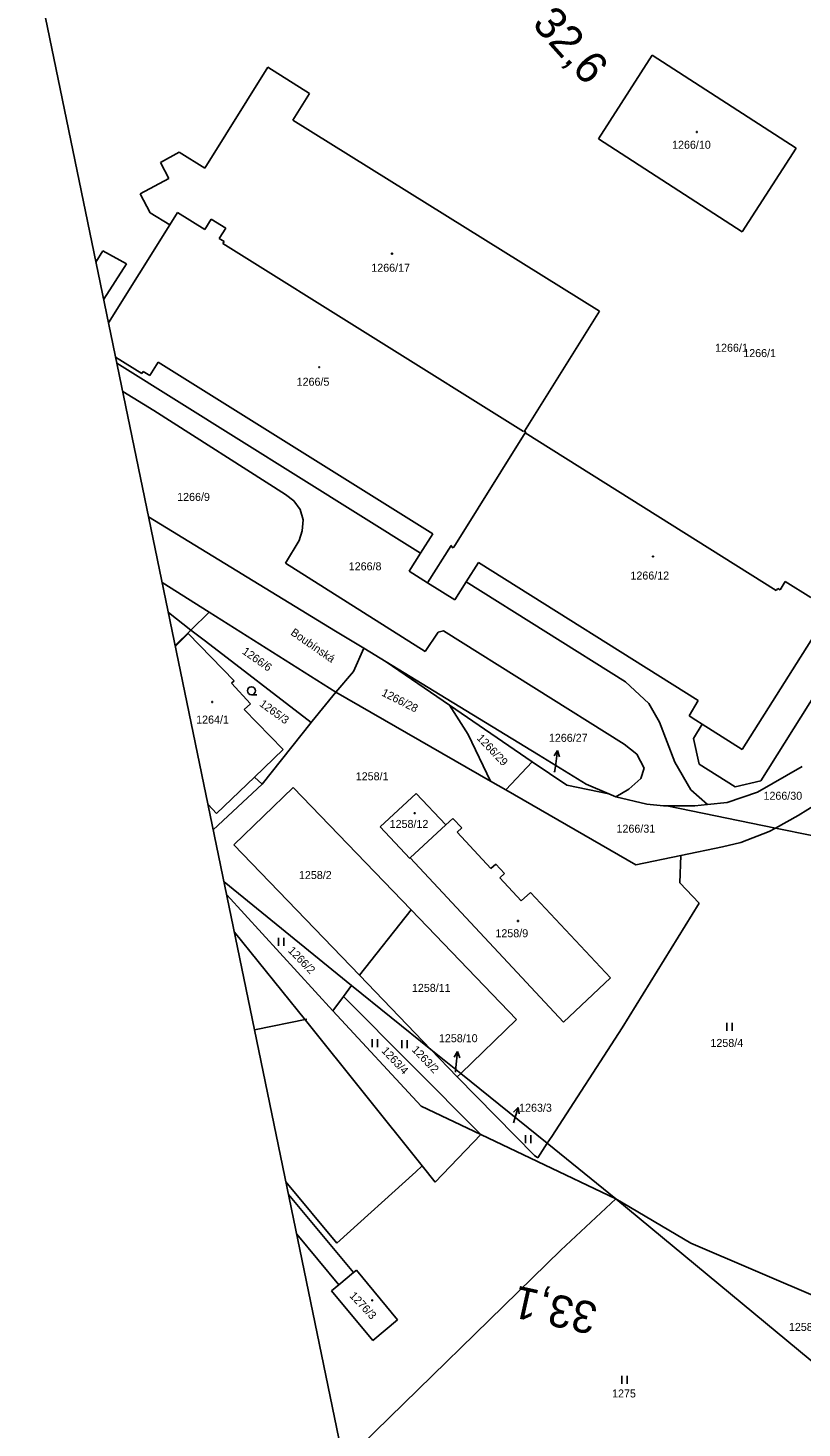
# Model space of a CAD drawing. Extents: x -804166 to -803706, y -1151030 to -1150147.
# Drawn here: x -804123.8 to -803978.8, y -1150693.3 to -1150430.9 of the extents above; entities that cross this region are included whole.
import ezdxf

# ---------------------------------------------------------------- set-up
doc = ezdxf.new("R2010")
doc.units = 0
for name, color, linetype in [('Default', 7, 'Continuous'), ('formát', 7, 'Continuous'), ('kilometráž - vrstava 7', 7, 'Continuous'), ('kn_celek - Cisla parcel pomocna', 7, 'Continuous'), ('kn_celek - Cisla pozemkovych parcel', 7, 'Continuous'), ('kn_celek - Cisla stavebnich parcel', 7, 'Continuous'), ('kn_celek - Dalsi prvky mapy popis', 7, 'Continuous'), ('kn_celek - Hranice parcel', 7, 'Continuous'), ('kn_celek - Vnitrni kresby', 7, 'Continuous'), ('kn_celek - Znacky budov', 7, 'Continuous'), ('kn_celek - Znacky kultur', 7, 'Continuous')]:
    doc.layers.add(name, color=color, linetype=linetype)

# ---------------------------------------------------------------- blocks, each defined once
blk = doc.blocks.new('306')
at = {"layer": 'Default'}
for p, q in [((-5.2, 0), (-5.2, 15)), ((4.8, 0), (4.8, 15))]:
    blk.add_line(p, q, dxfattribs=at)
blk = doc.blocks.new('304')
at = {"layer": 'Default'}
blk.add_line((-0.1, 0), (9.9, 0), dxfattribs=at)
blk.add_circle((-0.1, 7.5), 7.5, dxfattribs=at)
blk = doc.blocks.new('402')
at = {"layer": 'Default'}
for p, q in [((-0.8, 0.8), (0.7, 0.8)), ((-0.8, 0.8), (-0.8, -0.7)), ((0.7, 0.8), (0.7, -0.7)), ((0.7, -0.7), (-0.8, -0.7))]:
    blk.add_line(p, q, dxfattribs=at)
blk = doc.blocks.new('Z61')
at = {"layer": 'Default'}
for p, q in [((0, 0), (30, 0)), ((30, 0), (19.2, 5.3)), ((30, 0), (19.2, -5.3))]:
    blk.add_line(p, q, dxfattribs=at)

msp = doc.modelspace()

# ---------------------------------------------------------------- linework, layer by layer
at = {"layer": 'formát'}
for p, q in [((-804123.84, -1150413.06), (-804081.38, -1150618.72)), ((-804081.38, -1150618.72), (-804071.58, -1150616.7)), ((-804081.38, -1150618.72), (-803996.46, -1151030.05))]:
    msp.add_line(p, q, dxfattribs=at)
at = {"layer": 'kn_celek - Cisla parcel pomocna'}
for p, q in [((-804025.16, -1150570.39), (-804025.01, -1150569.34)), ((-804043.76, -1150626.64), (-804043.67, -1150625.78))]:
    msp.add_line(p, q, dxfattribs=at)
at = {"layer": 'kn_celek - Hranice parcel'}
for p, q in [((-804016.96, -1150451.69), (-804006.87, -1150436.01)), ((-804006.87, -1150436.01), (-803979.87, -1150453.43)), ((-804078.92, -1150438.26), (-804090.73, -1150457.18)), ((-804071.08, -1150443.16), (-804078.92, -1150438.26)), ((-804074.21, -1150448.18), (-804071.08, -1150443.16)), ((-804016.75, -1150484.01), (-804074.21, -1150448.18)), ((-803989.99, -1150469.12), (-804016.96, -1150451.69)), ((-804095.54, -1150454.21), (-804099.03, -1150456.1)), ((-804090.73, -1150457.18), (-804095.54, -1150454.21)), ((-803979.87, -1150453.43), (-803989.99, -1150469.12)), ((-804099.03, -1150456.1), (-804097.43, -1150459.12)), ((-804097.43, -1150459.12), (-804102.83, -1150461.99)), ((-804102.83, -1150461.99), (-804100.93, -1150465.54)), ((-804100.93, -1150465.54), (-804097.27, -1150467.82)), ((-804095.82, -1150465.49), (-804097.27, -1150467.82)), ((-804090.73, -1150468.69), (-804095.82, -1150465.49)), ((-804097.27, -1150467.82), (-804108.74, -1150486.17)), ((-804089.52, -1150466.74), (-804090.73, -1150468.69)), ((-804086.8, -1150468.43), (-804089.52, -1150466.74)), ((-804088.02, -1150470.38), (-804086.8, -1150468.43)), ((-804087.09, -1150470.96), (-804088.02, -1150470.38)), ((-804087.3, -1150471.3), (-804087.09, -1150470.96)), ((-804030.97, -1150506.52), (-804087.3, -1150471.3)), ((-804109.79, -1150472.7), (-804111.1, -1150474.78)), ((-804105.4, -1150475.1), (-804109.79, -1150472.7)), ((-804105.4, -1150475.1), (-804109.66, -1150481.72)), ((-804030.79, -1150506.51), (-804016.75, -1150484.01)), ((-804107.42, -1150492.59), (-804102.5, -1150495.66)), ((-804107.19, -1150493.72), (-804050.27, -1150529.35)), ((-804101.02, -1150496.07), (-804099.45, -1150493.57)), ((-804099.45, -1150493.57), (-804047.98, -1150525.74)), ((-804102.5, -1150495.66), (-804102.29, -1150495.28)), ((-804102.29, -1150495.28), (-804101.02, -1150496.07)), ((-804106.09, -1150499.03), (-804100.25, -1150502.6)), ((-804100.25, -1150502.6), (-804075.6, -1150518.36)), ((-804030.68, -1150506.78), (-804044.05, -1150528.23)), ((-804030.92, -1150506.44), (-804030.97, -1150506.52)), ((-804030.92, -1150506.44), (-804030.79, -1150506.51)), ((-804030.79, -1150506.51), (-804030.58, -1150506.63)), ((-804030.68, -1150506.78), (-804030.58, -1150506.63)), ((-803983.63, -1150536.38), (-804030.68, -1150506.78)), ((-804075.6, -1150518.36), (-804074.02, -1150519.53)), ((-804074.02, -1150519.53), (-804072.81, -1150521.15)), ((-804072.81, -1150521.15), (-804072.3, -1150523.12)), ((-804066.19, -1150543.95), (-804101.24, -1150522.52)), ((-804072.3, -1150523.12), (-804072.44, -1150525.14)), ((-804072.44, -1150525.14), (-804073.01, -1150527.01)), ((-804047.98, -1150525.74), (-804050.27, -1150529.35)), ((-804073.01, -1150527.01), (-804075.59, -1150531.2)), ((-804044.52, -1150527.91), (-804048.97, -1150534.9)), ((-804044.52, -1150527.91), (-804044.39, -1150527.99)), ((-804044.39, -1150527.99), (-804044.48, -1150528.14)), ((-804044.48, -1150528.14), (-804044.14, -1150528.37)), ((-804044.14, -1150528.37), (-804044.05, -1150528.23)), ((-804075.59, -1150531.2), (-804049.42, -1150547.8)), ((-804052.42, -1150532.75), (-804050.27, -1150529.35)), ((-804039.43, -1150531.11), (-804041.71, -1150534.74)), ((-803998.28, -1150556.97), (-804039.43, -1150531.11)), ((-804052.42, -1150532.75), (-804048.97, -1150534.9)), ((-804089.88, -1150540.41), (-804098.7, -1150534.84)), ((-804043.84, -1150538.13), (-804048.97, -1150534.9)), ((-804041.71, -1150534.74), (-804043.84, -1150538.13)), ((-804041.71, -1150534.74), (-804011.88, -1150553.48)), ((-803983.36, -1150535.95), (-803983.63, -1150536.38)), ((-803982.92, -1150536.23), (-803983.36, -1150535.95)), ((-803981.93, -1150534.66), (-803982.92, -1150536.23)), ((-803977.17, -1150537.66), (-803981.93, -1150534.66)), ((-804097.53, -1150540.5), (-804093.31, -1150543.76)), ((-804089.88, -1150540.41), (-804093.31, -1150543.76)), ((-804089.88, -1150540.41), (-804066.17, -1150555.39)), ((-804096.26, -1150546.65), (-804093.31, -1150543.76)), ((-804096.23, -1150546.77), (-804093.82, -1150544.42)), ((-804093.82, -1150544.42), (-804085.19, -1150553.27)), ((-804093.31, -1150543.76), (-804090.57, -1150545.83)), ((-804060.93, -1150547.17), (-804066.19, -1150543.95)), ((-804049.42, -1150547.8), (-804046.98, -1150544.17)), ((-804046.98, -1150544.17), (-804045.99, -1150543.91)), ((-804045.99, -1150543.91), (-804012.15, -1150565.18)), ((-804090.57, -1150545.83), (-804070.79, -1150561.09)), ((-804062.82, -1150551.55), (-804060.93, -1150547.17)), ((-804056.75, -1150549.72), (-804060.93, -1150547.17)), ((-803986.49, -1150572.01), (-803969.82, -1150545.4)), ((-804045.51, -1150556.6), (-804056.75, -1150549.72)), ((-804044.84, -1150557.87), (-804056.75, -1150549.72)), ((-804066.17, -1150555.39), (-804062.82, -1150551.55)), ((-804085.19, -1150553.27), (-804085.71, -1150553.75)), ((-804085.71, -1150553.75), (-804082.14, -1150557.58)), ((-804070.57, -1150560.82), (-804066.17, -1150555.39)), ((-804037.19, -1150572.09), (-804066.17, -1150555.39)), ((-804011.88, -1150553.48), (-804007.48, -1150557.53)), ((-804082.14, -1150557.58), (-804083.36, -1150558.66)), ((-804028.2, -1150567.18), (-804045.51, -1150556.6)), ((-804044.84, -1150557.87), (-804041.37, -1150563.36)), ((-804029.38, -1150568.44), (-804044.84, -1150557.87)), ((-804007.48, -1150557.53), (-804005.51, -1150561.04)), ((-803999.95, -1150559.82), (-803998.28, -1150556.97)), ((-804083.36, -1150558.66), (-804076.02, -1150566.18)), ((-803998.67, -1150560.68), (-803999.95, -1150559.82)), ((-803998.67, -1150560.68), (-803997.49, -1150561.43)), ((-804070.79, -1150561.09), (-804079.95, -1150572.68)), ((-804070.57, -1150560.82), (-804070.79, -1150561.09)), ((-804005.51, -1150561.04), (-804002.65, -1150568.53)), ((-803997.49, -1150561.43), (-803999.16, -1150564.07)), ((-804041.37, -1150563.36), (-804037.19, -1150572.09)), ((-804012.15, -1150565.18), (-804009.78, -1150567.05)), ((-803999.16, -1150564.07), (-803998.05, -1150568.92)), ((-804081.39, -1150571.32), (-804076.02, -1150566.18)), ((-804029.38, -1150568.44), (-804034.33, -1150573.74)), ((-804022.9, -1150572.87), (-804029.38, -1150568.44)), ((-804019.25, -1150572.65), (-804028.2, -1150567.18)), ((-804009.78, -1150567.05), (-804008.4, -1150569.67)), ((-804002.65, -1150568.53), (-803999.61, -1150573.7)), ((-804008.4, -1150569.67), (-804009.02, -1150571.59)), ((-803998.05, -1150568.92), (-803991.34, -1150573.13)), ((-803987.15, -1150574.13), (-803978.76, -1150569.37)), ((-804079.95, -1150572.68), (-804089.12, -1150581.24)), ((-804081.39, -1150571.32), (-804088.5, -1150578.14)), ((-804085.27, -1150584), (-804074.15, -1150573.25)), ((-804079.95, -1150572.68), (-804081.39, -1150571.32)), ((-804074.15, -1150573.25), (-804052.05, -1150596.22)), ((-804034.33, -1150573.74), (-804037.19, -1150572.09)), ((-804009.91, -1150587.8), (-804034.33, -1150573.74)), ((-804015.03, -1150574.48), (-804022.9, -1150572.87)), ((-804019.25, -1150572.65), (-804015.03, -1150574.48)), ((-804011.25, -1150573.61), (-804013.7, -1150575.06)), ((-804009.02, -1150571.59), (-804011.25, -1150573.61)), ((-803999.61, -1150573.7), (-803996.54, -1150576.47)), ((-803991.34, -1150573.13), (-803986.49, -1150572.01)), ((-804057.86, -1150580.66), (-804051.13, -1150574.38)), ((-804051.13, -1150574.38), (-804045.54, -1150580.31)), ((-804015.03, -1150574.48), (-804013.7, -1150575.06)), ((-804013.7, -1150575.06), (-804007.87, -1150576.4)), ((-804007.87, -1150576.4), (-804004.78, -1150576.71)), ((-803996.54, -1150576.47), (-803992.85, -1150576.07)), ((-803987.15, -1150574.13), (-803992.85, -1150576.07)), ((-803974.11, -1150575.13), (-803979.5, -1150578.55)), ((-804088.5, -1150578.14), (-804090.1, -1150576.46)), ((-804004.78, -1150576.71), (-804004.14, -1150576.71)), ((-804004.14, -1150576.71), (-803998.89, -1150576.73)), ((-803983.74, -1150580.89), (-804004.14, -1150576.71)), ((-803998.89, -1150576.73), (-803996.54, -1150576.47)), ((-803979.5, -1150578.55), (-803983.74, -1150580.89)), ((-804052.31, -1150586.58), (-804057.86, -1150580.66)), ((-804052.2, -1150586.48), (-804045.54, -1150580.31)), ((-804045.54, -1150580.31), (-804044.21, -1150579.08)), ((-804044.21, -1150579.08), (-804042.55, -1150580.86)), ((-804042.55, -1150580.86), (-804043.44, -1150581.68)), ((-803990.24, -1150583.6), (-803984.93, -1150581.55)), ((-803984.93, -1150581.55), (-803983.74, -1150580.89)), ((-803983.74, -1150580.89), (-803976.96, -1150582.28)), ((-804061.72, -1150608.48), (-804085.27, -1150584)), ((-804043.44, -1150581.68), (-804037.1, -1150588.46)), ((-803993.73, -1150584.41), (-803990.24, -1150583.6)), ((-804052.2, -1150586.48), (-804052.31, -1150586.58)), ((-804023.47, -1150617.24), (-804052.2, -1150586.48)), ((-804009.91, -1150587.8), (-804001.51, -1150586.04)), ((-804001.71, -1150591.16), (-804001.51, -1150586.04)), ((-804001.51, -1150586.04), (-803993.73, -1150584.41)), ((-804037.1, -1150588.46), (-804036.2, -1150587.63)), ((-804036.2, -1150587.63), (-804034.55, -1150589.42)), ((-804034.55, -1150589.42), (-804035.44, -1150590.24)), ((-804063.22, -1150610.38), (-804087.1, -1150590.99)), ((-804035.44, -1150590.24), (-804031.43, -1150594.53)), ((-803998.09, -1150594.95), (-804001.71, -1150591.16)), ((-804086.61, -1150593.39), (-804066.74, -1150615.12)), ((-804031.43, -1150594.53), (-804029.68, -1150592.95)), ((-804029.68, -1150592.95), (-804014.66, -1150608.98)), ((-804052.05, -1150596.22), (-804061.72, -1150608.48)), ((-804052.05, -1150596.22), (-804032.3, -1150616.75)), ((-804012.48, -1150618.32), (-803998.09, -1150594.95)), ((-804071.82, -1150616.91), (-804085.16, -1150600.4)), ((-804064.75, -1150612.44), (-804063.22, -1150610.38)), ((-804063.22, -1150610.38), (-804048.33, -1150622.39)), ((-804048.33, -1150622.39), (-804061.72, -1150608.48)), ((-804014.66, -1150608.98), (-804023.47, -1150617.24)), ((-804066.74, -1150615.12), (-804064.75, -1150612.44)), ((-804064.75, -1150612.44), (-804038.96, -1150638.33)), ((-804050.17, -1150633), (-804066.74, -1150615.12)), ((-804071.82, -1150616.91), (-804049.99, -1150644.23)), ((-804032.3, -1150616.75), (-804042.74, -1150626.9)), ((-804025.71, -1150638.73), (-804012.48, -1150618.32)), ((-804043.39, -1150627.53), (-804048.33, -1150622.39)), ((-804042.74, -1150626.9), (-804048.33, -1150622.39)), ((-804042.74, -1150626.9), (-804043.39, -1150627.53)), ((-804028.9, -1150642.28), (-804043.39, -1150627.53)), ((-804042.74, -1150626.9), (-804026.54, -1150639.97)), ((-804038.96, -1150638.33), (-804050.17, -1150633)), ((-804047.57, -1150647.28), (-804038.96, -1150638.33)), ((-804028.35, -1150643.39), (-804038.96, -1150638.33)), ((-804026.54, -1150639.97), (-804025.71, -1150638.73)), ((-804028.32, -1150642.67), (-804026.54, -1150639.97)), ((-804026.54, -1150639.97), (-804013.68, -1150650.38)), ((-804051.16, -1150645.3), (-804049.99, -1150644.23)), ((-804049.99, -1150644.23), (-804047.57, -1150647.28)), ((-804028.32, -1150642.67), (-804028.9, -1150642.28)), ((-804013.68, -1150650.38), (-804028.35, -1150643.39)), ((-804075.5, -1150647.21), (-804065.98, -1150658.69)), ((-804065.98, -1150658.69), (-804051.16, -1150645.3)), ((-804075.01, -1150649.56), (-804062.82, -1150664.2)), ((-804013.68, -1150650.38), (-804024.02, -1150660)), ((-804013.68, -1150650.38), (-803999.62, -1150658.69)), ((-803968.03, -1150688.27), (-804013.68, -1150650.38)), ((-804073.47, -1150657.01), (-804065.57, -1150666.5)), ((-804024.02, -1150660), (-804064.66, -1150699.72)), ((-803999.62, -1150658.69), (-803974.99, -1150669.28)), ((-804065.57, -1150666.5), (-804062.82, -1150664.2)), ((-804062.82, -1150664.2), (-804062.31, -1150663.77)), ((-804062.31, -1150663.77), (-804054.58, -1150673.04)), ((-804066.95, -1150667.66), (-804065.57, -1150666.5)), ((-804059.21, -1150676.92), (-804066.95, -1150667.66)), ((-804054.58, -1150673.04), (-804059.21, -1150676.92))]:
    msp.add_line(p, q, dxfattribs=at)
at = {"layer": 'kn_celek - Vnitrni kresby'}
for p, q in [((-803989.99, -1150566.17), (-803974.91, -1150542.21)), ((-803997.49, -1150561.43), (-803989.99, -1150566.17))]:
    msp.add_line(p, q, dxfattribs=at)

# ---------------------------------------------------------------- block references
at = {"layer": 'kn_celek - Cisla parcel pomocna'}
for p, xscale, yscale, rotation in [((-804025.01, -1150569.34), 0.1, 0.09999999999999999, 81.9297), ((-804043.67, -1150625.78), 0.1, 0.10000000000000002, 84.05316000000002), ((-804032.88, -1150636.15), 0.09999999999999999, 0.09999999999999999, 73.30086000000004)]:
    msp.add_blockref('Z61', p, dxfattribs=dict(at, xscale=xscale, yscale=yscale, rotation=rotation))
at = {"layer": 'kn_celek - Znacky budov', "xscale": 0.1, "yscale": 0.10000000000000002}
for p in [(-803998.51, -1150450.4), (-804055.62, -1150473.21), (-804069.28, -1150494.51), (-804006.72, -1150529.99), (-804089.33, -1150557.27), (-804051.39, -1150578.08), (-804032.02, -1150598.31), (-804059.35, -1150669.41)]:
    msp.add_blockref('402', p, dxfattribs=at)
at = {"layer": 'kn_celek - Znacky kultur', "xscale": 0.1, "yscale": 0.10000000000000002}
for name, p in [('304', (-804081.95, -1150555.89)), ('306', (-804076.37, -1150602.99)), ('306', (-803992.4, -1150618.9)), ('306', (-804058.82, -1150621.97)), ('306', (-804053.28, -1150622.16)), ('306', (-804030.09, -1150639.93)), ('306', (-804012.07, -1150685.07))]:
    msp.add_blockref(name, p, dxfattribs=at)

# ---------------------------------------------------------------- texts
at = {"layer": 'kilometráž - vrstava 7'}
for s, rotation, p in [('32,6', 311.8828, (-804029.55, -1150430.27)), ('33,1', 167.4012, (-804016.8, -1150670.05))]:
    msp.add_text(s, height=6, rotation=rotation, dxfattribs=at).set_placement(p)
at = {"layer": 'kn_celek - Cisla parcel pomocna'}
for s, p in [('1266/27', (-804026.23, -1150564.72)), ('1258/10', (-804046.84, -1150621.03)), ('1263/3', (-804031.81, -1150634.06))]:
    msp.add_text(s, height=1.5, dxfattribs=at).set_placement(p)
at = {"layer": 'kn_celek - Cisla pozemkovych parcel'}
for s, height, p in [('1266/1', 1.5, (-803995.09, -1150491.6)), ('1266/1', 1.5, (-803989.81, -1150492.6)), ('1266/9', 1.5, (-804095.89, -1150519.56)), ('1266/8', 1.5, (-804063.74, -1150532.57)), ('1258/1', 1.5, (-804062.42, -1150571.93)), ('1266/27', 0.1, (-804025.47, -1150570.36)), ('1266/30', 1.5, (-803986.02, -1150575.58)), ('1266/31', 1.5, (-804013.56, -1150581.74)), ('1258/2', 1.5, (-804073.07, -1150590.44)), ('1258/11', 1.5, (-804051.9, -1150611.59)), ('1258/4', 1.5, (-803995.96, -1150621.91)), ('1258/10', 0.1, (-804044.06, -1150626.61)), ('1263/3', 0.1, (-804032.88, -1150636.12)), ('1258/5', 1.5, (-803981.26, -1150675.15)), ('1275', 1.5, (-804014.39, -1150687.62))]:
    msp.add_text(s, height=height, dxfattribs=at).set_placement(p)
for s, rotation, p in [('1266/6', 324.9, (-804083.84, -1150548.08)), ('1266/28', 333.1986, (-804057.71, -1150555.99)), ('1265/3', 324, (-804080.59, -1150557.88)), ('1266/29', 313.7083, (-804039.85, -1150564.13)), ('1266/2', 314.1, (-804075.21, -1150603.96)), ('1263/4', 313.2673, (-804057.7, -1150622.73)), ('1263/2', 313.6896, (-804052.02, -1150622.54))]:
    msp.add_text(s, height=1.5, rotation=rotation, dxfattribs=at).set_placement(p)
at = {"layer": 'kn_celek - Cisla stavebnich parcel'}
for s, p in [('1266/10', (-804003.15, -1150453.55)), ('1266/17', (-804059.51, -1150476.6)), ('1266/5', (-804073.5, -1150497.97)), ('1266/12', (-804010.95, -1150534.3)), ('1264/1', (-804092.33, -1150561.3)), ('1258/12', (-804056.07, -1150580.86)), ('1258/9', (-804036.25, -1150601.35))]:
    msp.add_text(s, height=1.5, dxfattribs=at).set_placement(p)
msp.add_text('1276/3', height=1.5, rotation=313.189, dxfattribs=at).set_placement((-804063.7, -1150668.65))
at = {"layer": 'kn_celek - Dalsi prvky mapy popis'}
msp.add_text('Boubínská', height=1.5, rotation=325.0319, dxfattribs=at).set_placement((-804074.75, -1150544.54))

doc.saveas('drawing.dxf')
